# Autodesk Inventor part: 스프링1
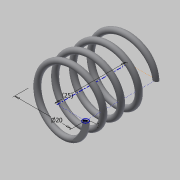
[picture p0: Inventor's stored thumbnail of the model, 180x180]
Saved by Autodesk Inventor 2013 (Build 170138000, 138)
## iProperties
Created: 2016-07
Part Number: 스프링1
Material: 스테인리스강
Document SubType Name: Modeling
Designer: dgall
Density: 8.08 g/cm^3
Mass: 6.25982 g
Surface Area: 15.7247 cm^2
Volume: 0.77473 cm^3
Author: dgall
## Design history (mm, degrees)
sketch "스케치1"
  geometry: L1 (0, 0)-(10, 0); L2 (10, 0)-(10, 19.5); L3 (10, 19.5)-(0, 19.5); L4 (0, 19.5)-(0, 0); C1 r 1 at (10, 0)
  constraints: 8 end point, 2 parallel, 1 centre point, 1 coincident, 1 horizontal, 1 perpendicular
  dimensions: "d0" = 2 diameter of C1; "d2" = 19.5 distance of L3.end L1.start (derived); "d3" = 20 diameter of L2 L4
feature "코일1" sketch "스케치1" pitch "d4" = 10; turns "d6" = 4; dims "d5" = 19.5 (= d2), "d7" = 0, angle "d8" = 90 deg, angle "d9" = 90 deg, "d10" = 0, "d11" = 0
feature "분할1"
node "작업 평면1"
feature "분할2"
node "솔리드1"
